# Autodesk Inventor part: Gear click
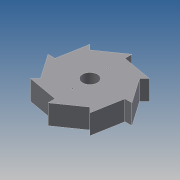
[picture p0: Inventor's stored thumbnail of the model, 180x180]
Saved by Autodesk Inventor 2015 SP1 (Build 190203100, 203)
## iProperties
Created: 2015-01
Part Number: Gear click
Material: Generic
Document SubType Name: Modeling
Designer: Steve Brooks
Density: 1 g/cm^3
Appearance: Default
Author: Steve Brooks
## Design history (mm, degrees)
sketch "Sketch1"
  geometry: L1 (0.416, 18.168)-(0.416, 18.178); L2 (0.416, -13.582)-(0.416, -13.572); L3 (22.865, 24.747)-(27.356, 29.237); L4 (27.356, 29.237)-(0.416, 34.033); L5 (0.416, 34.033)-(0.416, 40.388); L6 (0.416, 40.388)-(-22.027, 24.742); L7 (-22.027, 24.742)-(-26.518, 29.232); L8 (-26.518, 29.232)-(-31.329, 2.298); L9 (-31.329, 2.298)-(-37.679, 2.298); L10 (-37.679, 2.298)-(-22.032, -20.15); L11 (-22.032, -20.15)-(-26.523, -24.641); L12 (-26.523, -24.641)-(0.416, -29.437); L13 (0.416, -29.437)-(0.416, -35.792); L14 (0.416, -35.792)-(22.86, -20.145); L15 (22.86, -20.145)-(27.35, -24.636); L16 (27.35, -24.636)-(32.161, 2.298); L17 (32.161, 2.298)-(38.511, 2.298); L18 (38.511, 2.298)-(22.865, 24.747); C1 r 6.747 at (0.416, 2.298); 3 further points; 2 other entities
  constraints: 36 end point, 1 centre point, 4 other
extrude "Extrusion1" new body sketch "Sketch1" distance "d0" = 18; taper "d1" = 0 deg
body "Solid1"
